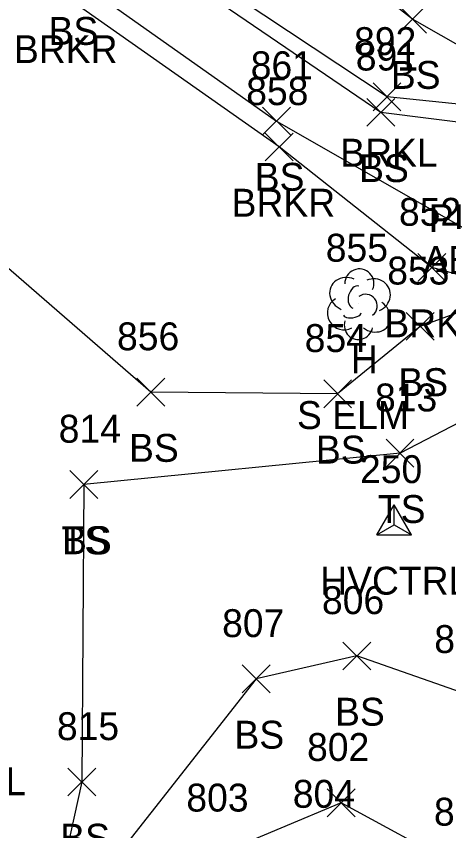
# Model space of a CAD drawing. Extents: x 1639430 to 1640195, y 612006 to 612917.
# Drawn here: x 1639766.2 to 1639797.2, y 612574.5 to 612632.9 of the extents above; entities that cross this region are included whole.
import ezdxf

# ---------------------------------------------------------------- set-up
doc = ezdxf.new("R2010")
doc.units = 0
for name, color, linetype in [('C_A', 7, 'Continuous'), ('C_I', 7, 'Continuous'), ('CPSM', 7, 'Continuous'), ('D_C', 7, 'Continuous'), ('L_A', 7, 'Continuous'), ('L_C', 7, 'Continuous'), ('L_I', 7, 'Continuous'), ('L_TIC', 7, 'Continuous'), ('LAWE', 7, 'Continuous'), ('LELB', 7, 'Continuous'), ('LTD', 7, 'Continuous'), ('U_I', 7, 'Continuous')]:
    doc.layers.add(name, color=color, linetype=linetype)

msp = doc.modelspace()

# ---------------------------------------------------------------- linework, layer by layer
at = {"layer": 'CPSM'}
for p, q in [((1639792.07, 612595.706), (1639793.32, 612597.871)), ((1639794.57, 612595.706), (1639793.32, 612597.871)), ((1639793.32, 612596.427), (1639793.32, 612597.871)), ((1639792.07, 612595.706), (1639793.32, 612596.427)), ((1639793.32, 612596.427), (1639793.32, 612596.427)), ((1639793.32, 612596.427), (1639794.57, 612595.706)), ((1639792.07, 612595.706), (1639794.57, 612595.706))]:
    msp.add_line(p, q, dxfattribs=at)
at = {"layer": 'L_TIC'}
for points in [[(1639793.64, 612631.699), (1639795.64, 612633.699)], [(1639795.64, 612631.699), (1639793.64, 612633.699)], [(1639791.808, 612626.122), (1639793.808, 612628.122)], [(1639793.808, 612626.122), (1639791.808, 612628.122)], [(1639791.365, 612625.015), (1639793.365, 612627.015)], [(1639793.365, 612625.015), (1639791.365, 612627.015)], [(1639783.877, 612624.393), (1639785.877, 612626.393)], [(1639785.877, 612624.393), (1639783.877, 612626.393)], [(1639784.071, 612622.534), (1639786.071, 612624.534)], [(1639786.071, 612622.534), (1639784.071, 612624.534)], [(1639795.025, 612613.881), (1639797.025, 612615.881)], [(1639797.025, 612613.881), (1639795.025, 612615.881)], [(1639794.184, 612609.668), (1639796.184, 612611.668)], [(1639796.184, 612609.668), (1639794.184, 612611.668)], [(1639774.865, 612604.953), (1639776.865, 612606.953)], [(1639776.865, 612604.953), (1639774.865, 612606.953)], [(1639788.267, 612604.827), (1639790.267, 612606.827)], [(1639790.267, 612604.827), (1639788.267, 612606.827)], [(1639792.742, 612600.568), (1639794.742, 612602.568)], [(1639794.742, 612600.568), (1639792.742, 612602.568)], [(1639770.061, 612598.326), (1639772.061, 612600.326)], [(1639772.061, 612598.326), (1639770.061, 612600.326)], [(1639770.061, 612598.326), (1639772.061, 612600.326)], [(1639772.061, 612598.326), (1639770.061, 612600.326)], [(1639789.638, 612586.031), (1639791.638, 612588.031)], [(1639791.638, 612586.031), (1639789.638, 612588.031)], [(1639782.425, 612584.383), (1639784.425, 612586.383)], [(1639784.425, 612584.383), (1639782.425, 612586.383)], [(1639769.93, 612576.995), (1639771.93, 612578.995)], [(1639771.93, 612576.995), (1639769.93, 612578.995)], [(1639788.515, 612575.502), (1639790.515, 612577.502)], [(1639790.515, 612575.502), (1639788.515, 612577.502)]]:
    msp.add_lwpolyline(points, dxfattribs=at)
at = {"layer": 'LAWE'}
for points in [[(1639818.397, 612622.252), (1639806.958, 612625.66), (1639792.808, 612627.122), (1639771.525, 612641.248)], [(1639815.502, 612605.955), (1639811.555, 612610.222), (1639810.816, 612611.799), (1639809.099, 612612.433), (1639807.886, 612612.157), (1639806.874, 612611.255), (1639802.154, 612613.218), (1639796.025, 612614.881), (1639785.071, 612623.534), (1639769.465, 612634.546)]]:
    msp.add_lwpolyline(points, dxfattribs=at)
at = {"layer": 'LELB'}
for points in [[(1639806.958, 612625.66), (1639794.64, 612632.699), (1639782.07, 612642.52), (1639774.976, 612651.801)], [(1639764.188, 612527.424), (1639772.977, 612544.039), (1639792.096, 612560.955), (1639798.045, 612571.861), (1639798.637, 612584.242), (1639801.408, 612590.442), (1639806.01, 612591.217), (1639813.347, 612604.755), (1639814.159, 612604.989), (1639815.502, 612605.955), (1639817.508, 612607.626), (1639823.926, 612612.002), (1639825.414, 612614.447), (1639825.954, 612618.423), (1639826.214, 612622.256), (1639826.372, 612626.105), (1639824.294, 612621.683), (1639822.313, 612620.482), (1639821.077, 612619.388), (1639821.02, 612619.326), (1639817.573, 612621.321), (1639806.603, 612624.212), (1639792.365, 612626.015), (1639770.728, 612640.749)], [(1639770.094, 612635.855), (1639784.877, 612625.393), (1639800.41, 612616.513), (1639807.846, 612612.518), (1639809.601, 612612.895), (1639810.878, 612612.379), (1639816.171, 612610.009), (1639817.508, 612607.626)], [(1639802.154, 612613.218), (1639795.184, 612610.668), (1639789.267, 612605.827), (1639775.865, 612605.953), (1639759.097, 612620.5)], [(1639813.347, 612604.755), (1639804.109, 612606.948), (1639793.742, 612601.568), (1639771.061, 612599.326)], [(1639771.061, 612599.326), (1639770.93, 612577.995), (1639768.307, 612566.176)], [(1639798.637, 612584.242), (1639790.638, 612587.031), (1639783.425, 612585.383), (1639768.307, 612566.176), (1639755.346, 612547.014), (1639737.305, 612513.749)], [(1639798.045, 612571.861), (1639789.515, 612576.502), (1639780.858, 612572.873), (1639771.52, 612563.119), (1639755.346, 612547.014)]]:
    msp.add_lwpolyline(points, dxfattribs=at)
at = {"layer": 'LTD'}
msp.add_line((1639790.777, 612612.306), (1639790.777, 612612.306), dxfattribs=at)
msp.add_line((1639790.777, 612612.306), (1639790.777, 612612.306), dxfattribs=at)
msp.add_arc((1639790.824, 612613.74), 1.047, 335.52715, 180.95627, dxfattribs=at)
for centre, major_axis, ratio, start_param, end_param in [((1639789.985, 612612.972), (1.21, -0.512), 0.895232, 1.570796, 4.712389), ((1639791.818, 612612.889), (-1.141, -0.483), 0.949671, 1.570796, 4.712389), ((1639790.568, 612612.764), (-0.208, -0.792), 0.645439, 3.141593, 6.283185), ((1639791.277, 612612.139), (-0.5, 0.667), 0.989748, 3.141593, 6.283185), ((1639789.694, 612611.597), (0.584, -1.042), 0.959034, 3.141593, 6.283185), ((1639791.777, 612611.473), (-1.09, 0.792), 0.841452, 1.570796, 4.712389), ((1639790.319, 612611.556), (-0.625, -0.083), 0.423636, 0, 3.141593), ((1639790.777, 612610.806), (0.265, 1.061), 0.942809, 1.570796, 4.712389)]:
    msp.add_ellipse(centre, major_axis=major_axis, ratio=ratio, start_param=start_param, end_param=end_param, dxfattribs=at)

# ---------------------------------------------------------------- texts
at = {"layer": 'C_A'}
msp.add_text('HVCTRL', height=2, dxfattribs=at).set_placement((1639788.013, 612591.427))
at = {"layer": 'C_I'}
msp.add_text('250', height=2, dxfattribs=at).set_placement((1639790.871, 612599.427))
at = {"layer": 'D_C'}
for s, p in [('PIPE IS SUSPENDED', (1639795.8, 612617.427)), ('ABOVE THE GROUND', (1639795.406, 612614.427))]:
    msp.add_text(s, height=2, dxfattribs=at).set_placement(p)
at = {"layer": 'L_A'}
for s, p in [('BS', (1639768.535, 612630.855)), ('BRKR', (1639766.056, 612629.546)), ('BS', (1639793.081, 612627.699)), ('BRKL', (1639789.454, 612622.122)), ('BS', (1639790.806, 612621.015)), ('BS', (1639783.318, 612620.393)), ('BRKR', (1639781.662, 612618.534)), ('BRKR', (1639792.616, 612609.881)), ('H', (1639790.21, 612607.306)), ('BS', (1639793.625, 612605.668)), ('BS', (1639774.306, 612600.953)), ('BS', (1639787.708, 612600.827)), ('TS', (1639792.152, 612596.568)), ('TS', (1639769.471, 612594.326)), ('BS', (1639769.502, 612594.326)), ('BS', (1639789.079, 612582.031)), ('BS', (1639781.866, 612580.383)), ('BRL', (1639761.722, 612577.042)), ('BS', (1639769.371, 612572.995))]:
    msp.add_text(s, height=2, dxfattribs=at).set_placement(p)
at = {"layer": 'L_C'}
msp.add_text('S ELM', height=2, dxfattribs=at).set_placement((1639786.352, 612603.306))
at = {"layer": 'L_I'}
for s, p in [('892', (1639790.446, 612630.122)), ('891', (1639790.569, 612629.015)), ('861', (1639783.034, 612628.393)), ('858', (1639782.709, 612626.534)), ('852', (1639793.663, 612617.881)), ('855', (1639788.415, 612615.306)), ('853', (1639792.822, 612613.668)), ('856', (1639773.447, 612608.953)), ('854', (1639786.905, 612608.827)), ('813', (1639791.947, 612604.568)), ('814', (1639769.266, 612602.326)), ('814', (1639769.266, 612602.326)), ('806', (1639788.142, 612590.031)), ('807', (1639780.984, 612588.383)), ('805', (1639796.196, 612587.242)), ('805', (1639796.196, 612587.242)), ('815', (1639769.135, 612580.995)), ('802', (1639787.074, 612579.502)), ('803', (1639778.417, 612575.873)), ('801', (1639796.171, 612574.861)), ('801', (1639796.171, 612574.861))]:
    msp.add_text(s, height=2, dxfattribs=at).set_placement(p)
at = {"layer": 'U_I'}
msp.add_text('804', height=2, dxfattribs=at).set_placement((1639786.052, 612576.143))

doc.saveas('drawing.dxf')
